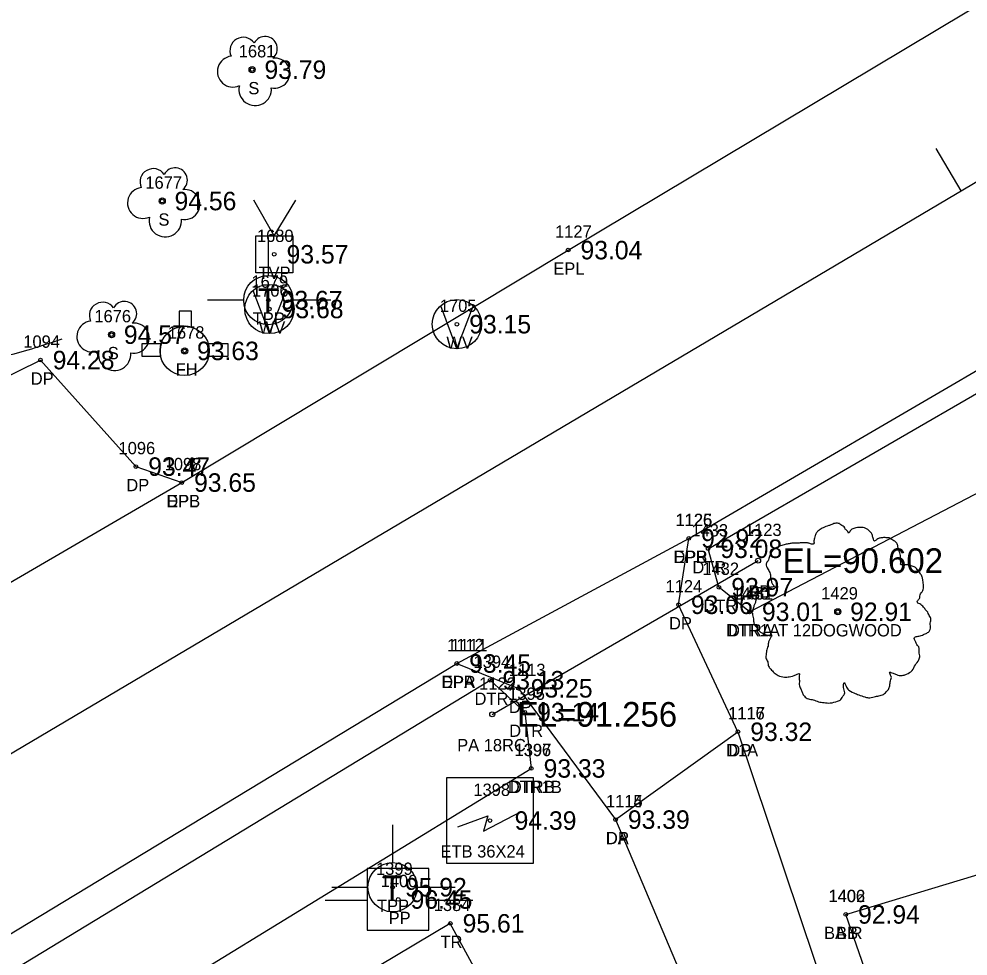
# Model space of a CAD drawing. Extents: x 2529517 to 2532038, y 935000 to 936944.
# Drawn here: x 2530911.6 to 2530988.7, y 935818.5 to 935894.6 of the extents above; entities that cross this region are included whole.
import ezdxf

# ---------------------------------------------------------------- set-up
doc = ezdxf.new("R2010")
doc.units = 0
for name, color, linetype in [('Default', 7, 'Continuous'), ('RD_EX_Bldg', 7, 'Continuous'), ('RD_EX_Bldg_txCode', 7, 'Continuous'), ('RD_EX_BldgApp', 7, 'Continuous'), ('RD_EX_DR_Pipe', 7, 'Continuous'), ('RD_EX_DR_Pipe_txCode', 7, 'Continuous'), ('RD_EX_Driveway', 7, 'Continuous'), ('RD_EX_Driveway_txCode', 7, 'Continuous'), ('RD_EX_H2O', 7, 'Continuous'), ('RD_EX_H2O_txCode', 7, 'Continuous'), ('RD_EX_Road', 7, 'Continuous'), ('RD_EX_Road_txCode', 7, 'Continuous'), ('RD_EX_TX_Bldg_ELEV', 7, 'Continuous'), ('RD_EX_TX_Driveway_ELEV', 7, 'Continuous'), ('RD_EX_TX_H2O_ELEV', 7, 'Continuous'), ('RD_EX_TX_Road_ELEV', 7, 'Continuous'), ('RD_EX_TX_UT_ELEV', 7, 'Continuous'), ('RD_EX_TX_VEG_ELEV', 7, 'Continuous'), ('RD_EX_UT', 7, 'Continuous'), ('RD_EX_UT_txCode', 7, 'Continuous'), ('RD_EX_VEG', 7, 'Continuous'), ('RD_EX_VEG_txCode', 7, 'Continuous'), ('RD_HC_Cl', 7, 'Continuous'), ('RD_HC_Data_Tic', 7, 'Continuous'), ('RD_HC_Survey_ELEV', 7, 'Continuous'), ('RD_SMD_Locator', 7, 'Continuous'), ('RD_TX_Pipe_ElevEX', 7, 'Continuous')]:
    doc.layers.add(name, color=color, linetype=linetype)

msp = doc.modelspace()

# ---------------------------------------------------------------- linework, layer by layer
at = {"layer": 'Default'}
msp.add_line((2530557.048, 935625.341), (2531768.068, 936342.554), dxfattribs=at)
at = {"layer": 'RD_EX_Bldg'}
msp.add_lwpolyline([(2530978.74, 935821.888), (2531008.107, 935830.756), (2531025.169, 935791.245), (2530993.411, 935779.732), (2530978.74, 935821.888)], dxfattribs=at)
at = {"layer": 'RD_EX_BldgApp'}
msp.add_open_spline([(2530899.082, 935867.283), (2530901.086, 935868.382), (2530905.768, 935865.432), (2530915.133, 935868.613)], degree=2, dxfattribs=at)
at = {"layer": 'RD_EX_DR_Pipe'}
msp.add_line((2530950.041, 935838.132), (2530971.625, 935850.61), dxfattribs=at)
at = {"layer": 'RD_EX_Driveway'}
for points in [[(2530835.179, 935834.103), (2530836.459, 935832.711), (2530846.318, 935840.723), (2530852.092, 935850.74), (2530868.321, 935858.234), (2530887.307, 935854.067), (2530913.359, 935866.894), (2530921.115, 935858.246), (2530924.837, 935856.951)], [(2530947.168, 935842.26), (2530952.171, 935840.244), (2530960.057, 935829.588), (2530969.992, 935836.718), (2530965.176, 935847.029), (2530966.001, 935852.419)], [(2530969.992, 935836.718), (2530982.506, 935799.382), (2530996.456, 935758.017)], [(2530960.057, 935829.588), (2530973.324, 935798.15), (2530986.134, 935754.257)]]:
    msp.add_lwpolyline(points, dxfattribs=at)
at = {"layer": 'RD_EX_H2O'}
msp.add_line((2530970.94, 935846.455), (2530996.778, 935859.952), dxfattribs=at)
for points in [[(2530970.94, 935846.455), (2530968.45, 935848.455), (2530967.561, 935851.576), (2530992.627, 935866.076), (2530995.026, 935864.088), (2530996.778, 935859.952)], [(2530882.813, 935800.188), (2530949.875, 935840.903), (2530952.688, 935838.305), (2530953.214, 935833.742)], [(2530882.813, 935800.188), (2530888.21, 935794.647), (2530891.364, 935795.844), (2530953.214, 935833.742)]]:
    msp.add_lwpolyline(points, dxfattribs=at)
at = {"layer": 'RD_EX_Road'}
for points in [[(2530213.129, 935600.159), (2530313.796, 935600.808), (2530414.146, 935601.135), (2530426.724, 935601.431), (2530429.462, 935603.551), (2530467.667, 935608.622), (2530486.463, 935612.382), (2530518.022, 935622.553), (2530522.163, 935623.679), (2530567.909, 935646.012), (2530609.299, 935670.154), (2530695.461, 935720.024), (2530775.853, 935769.269), (2530868.285, 935824.026), (2530924.837, 935856.951), (2530956.207, 935875.821), (2531040.717, 935926.378), (2531079.452, 935947.762)], [(2530212.444, 935579.718), (2530312.608, 935580.142), (2530402.982, 935580.636), (2530451.057, 935579.535), (2530466.913, 935580.348), (2530487.453, 935583.291), (2530533.43, 935598.455), (2530580.282, 935625.084), (2530621.694, 935649.225), (2530704.615, 935698.354), (2530718.668, 935706.376), (2530795.45, 935752.358), (2530871.328, 935796.67), (2530882.405, 935803.04), (2530947.168, 935842.26), (2530966.001, 935852.419), (2530992.723, 935868.002), (2531009.487, 935879.014), (2531052.394, 935904.854), (2531090.884, 935928.231)]]:
    msp.add_lwpolyline(points, dxfattribs=at)
at = {"layer": 'RD_EX_UT'}
for p, q in [((2530932.348, 935876.983), (2530930.682, 935879.869)), ((2530932.348, 935876.983), (2530934.089, 935879.869)), ((2530931.865, 935876.835), (2530931.865, 935873.765)), ((2530931.951, 935869.049), (2530930.647, 935872.531)), ((2530931.951, 935869.049), (2530933.273, 935872.494)), ((2530926.934, 935871.78), (2530929.865, 935871.78)), ((2530933.865, 935871.78), (2530936.934, 935871.78)), ((2530947.176, 935867.815), (2530945.872, 935871.297)), ((2530947.176, 935867.815), (2530948.498, 935871.26)), ((2530924.618, 935870.861), (2530924.618, 935869.587)), ((2530925.618, 935870.861), (2530924.618, 935870.861)), ((2530925.618, 935869.564), (2530925.618, 935870.861)), ((2530923.159, 935868.213), (2530921.601, 935868.213)), ((2530921.601, 935868.213), (2530921.601, 935867.213)), ((2530928.601, 935868.213), (2530926.991, 935868.213)), ((2530928.601, 935867.213), (2530928.601, 935868.213)), ((2530921.601, 935867.213), (2530923.121, 935867.213)), ((2530927.029, 935867.213), (2530928.601, 935867.213)), ((2530941.956, 935829.167), (2530941.956, 935826.098)), ((2530944.902, 935825.611), (2530939.902, 935825.611)), ((2530939.902, 935825.611), (2530939.902, 935820.611)), ((2530944.902, 935820.611), (2530944.902, 935825.611)), ((2530937.026, 935824.113), (2530939.956, 935824.113)), ((2530943.956, 935824.113), (2530947.026, 935824.113)), ((2530936.471, 935823.048), (2530939.94, 935823.048)), ((2530944.831, 935823.048), (2530948.471, 935823.048)), ((2530939.902, 935820.611), (2530944.902, 935820.611))]:
    msp.add_line(p, q, dxfattribs=at)
for points in [[(2530930.848, 935873.983), (2530930.848, 935876.983), (2530933.848, 935876.983), (2530933.848, 935873.983)], [(2530946.361, 935826.01), (2530946.361, 935833.01), (2530953.361, 935833.01), (2530953.361, 935826.01)]]:
    msp.add_lwpolyline(points, close=True, dxfattribs=at)
msp.add_lwpolyline([(2530947.26, 935829.004), (2530949.682, 935829.904), (2530949.336, 935828.658), (2530952.381, 935830.251)], dxfattribs=at)
for centre, radius in [((2530931.865, 935871.765), 2), ((2530931.951, 935871.041), 2), ((2530947.176, 935869.808), 2), ((2530925.075, 935867.64), 2), ((2530925.075, 935867.64), 0.25), ((2530941.956, 935824.098), 2)]:
    msp.add_circle(centre, radius, dxfattribs=at)
for start, end in [(74.24553, 103.21276), (163.3387, 192.31502), (347.68498, 16.6613)]:
    msp.add_arc((2530925.075, 935867.64), 2, start, end, dxfattribs=at)
at = {"layer": 'RD_EX_VEG'}
msp.add_lwpolyline([(2530909.492, 935692.948), (2530983.63, 935753.484), (2530946.64, 935821.165), (2530904.977, 935796.341), (2530852.836, 935733.758), (2530882.898, 935682.258)], dxfattribs=at)
for centre, radius in [((2530930.551, 935890.469), 0.25), ((2530923.252, 935879.805), 0.25), ((2530919.138, 935868.959), 0.25), ((2530978.099, 935846.458), 0.25), ((2530978.086, 935846.439), 0.0001)]:
    msp.add_circle(centre, radius, dxfattribs=at)
for centre, radius, start, end in [((2530929.83, 935892.016), 1.084, 34.97629, 204.75602), ((2530931.596, 935892.171), 0.995, 308.76261, 152.04674), ((2530928.987, 935890.314), 1.257, 96.45179, 294.73401), ((2530932.391, 935890.19), 1.218, 256.56668, 98.10463), ((2530930.797, 935888.873), 1.318, 166.88266, 5.75893), ((2530922.531, 935881.352), 1.084, 34.97629, 204.75602), ((2530924.297, 935881.507), 0.995, 308.76261, 152.04674), ((2530921.688, 935879.649), 1.257, 96.45179, 294.73401), ((2530925.092, 935879.525), 1.218, 256.56668, 98.10463), ((2530923.498, 935878.208), 1.318, 166.88266, 5.75893), ((2530918.417, 935870.506), 1.084, 34.97629, 204.75602), ((2530920.183, 935870.661), 0.995, 308.76261, 152.04674), ((2530917.574, 935868.803), 1.257, 96.45179, 294.73401), ((2530920.977, 935868.68), 1.218, 256.56668, 98.10463), ((2530919.383, 935867.363), 1.318, 166.88266, 5.75893)]:
    msp.add_arc(centre, radius, start, end, dxfattribs=at)
for points in [[(2530978.231, 935853.626), (2530977.931, 935853.651), (2530977.606, 935853.551), (2530977.356, 935853.451), (2530977.131, 935853.376), (2530976.906, 935853.276), (2530976.606, 935853.101), (2530976.382, 935852.901), (2530976.257, 935852.651), (2530976.207, 935852.426), (2530976.157, 935852.151), (2530976.157, 935851.976), (2530976.032, 935851.951), (2530975.882, 935851.976), (2530975.632, 935852.051), (2530975.382, 935852.051), (2530975.132, 935852.051), (2530974.782, 935852.026), (2530974.432, 935852.026), (2530974.158, 935851.976), (2530973.833, 935851.926), (2530973.458, 935851.801), (2530973.108, 935851.676), (2530972.808, 935851.426), (2530972.558, 935850.952), (2530972.433, 935850.602), (2530972.283, 935850.352), (2530972.433, 935849.902), (2530972.608, 935849.552), (2530972.633, 935849.352), (2530972.708, 935848.928), (2530972.808, 935848.703), (2530972.933, 935848.503), (2530972.858, 935848.478), (2530972.483, 935848.428), (2530972.183, 935848.328), (2530971.759, 935848.103), (2530971.534, 935847.878), (2530971.434, 935847.553), (2530971.409, 935847.203), (2530971.309, 935847.003), (2530971.234, 935846.729), (2530971.209, 935846.654), (2530971.159, 935846.329), (2530971.259, 935845.879), (2530971.284, 935845.529), (2530971.409, 935845.304), (2530971.559, 935845.129), (2530971.734, 935844.879), (2530972.133, 935844.654), (2530972.458, 935844.554), (2530972.658, 935844.53), (2530972.483, 935844.03), (2530972.433, 935843.68), (2530972.308, 935843.28), (2530972.308, 935843.205), (2530972.258, 935842.73), (2530972.408, 935842.405), (2530972.483, 935842.031), (2530972.658, 935841.806), (2530972.933, 935841.506), (2530973.258, 935841.281), (2530973.758, 935841.156), (2530974.158, 935841.181), (2530974.732, 935841.356), (2530974.982, 935841.431), (2530974.957, 935841.256), (2530974.982, 935840.881), (2530974.982, 935840.456), (2530975.132, 935840.131), (2530975.232, 935839.857), (2530975.382, 935839.607), (2530975.707, 935839.382), (2530976.107, 935839.307), (2530976.531, 935839.157), (2530976.981, 935839.082), (2530977.481, 935839.057), (2530978.081, 935839.207), (2530978.356, 935839.332), (2530978.456, 935839.507), (2530978.656, 935839.882), (2530978.606, 935840.106), (2530978.631, 935840.706), (2530978.73, 935840.531), (2530978.905, 935840.181), (2530979.405, 935839.882), (2530979.805, 935839.707), (2530980.28, 935839.557), (2530980.58, 935839.482), (2530981.054, 935839.557), (2530981.429, 935839.632), (2530981.804, 935839.757), (2530982.104, 935840.031), (2530982.279, 935840.306), (2530982.329, 935840.581), (2530982.404, 935840.956), (2530982.454, 935841.131)], [(2530982.454, 935841.131), (2530982.379, 935841.306), (2530982.329, 935841.556), (2530982.404, 935841.531), (2530982.579, 935841.481), (2530982.854, 935841.356), (2530983.079, 935841.281), (2530983.403, 935841.306), (2530983.678, 935841.406), (2530984.128, 935841.681), (2530984.403, 935842.156), (2530984.678, 935842.555), (2530984.753, 935842.88), (2530984.703, 935843.105), (2530984.678, 935843.605), (2530984.478, 935843.855), (2530984.428, 935843.98), (2530984.328, 935844.38), (2530984.403, 935844.43), (2530984.678, 935844.48), (2530985.053, 935844.604), (2530985.328, 935844.729), (2530985.553, 935844.904), (2530985.627, 935845.129), (2530985.603, 935845.529), (2530985.652, 935845.929), (2530985.578, 935846.079), (2530985.478, 935846.229), (2530985.403, 935846.429), (2530985.253, 935846.579), (2530985.153, 935846.729), (2530985.053, 935846.828), (2530984.928, 935846.978), (2530984.753, 935847.103), (2530984.603, 935847.153), (2530984.553, 935847.303), (2530984.703, 935847.503), (2530984.753, 935847.603), (2530984.778, 935847.828), (2530985.003, 935848.178), (2530985.053, 935848.578), (2530985.003, 935849.003), (2530984.953, 935849.277), (2530984.803, 935849.552), (2530984.603, 935849.802), (2530984.478, 935849.977), (2530984.303, 935850.102), (2530983.978, 935850.227), (2530983.728, 935850.277), (2530983.378, 935850.277), (2530983.179, 935850.327), (2530983.204, 935850.377), (2530983.204, 935850.527), (2530983.204, 935850.802), (2530983.129, 935851.252), (2530982.979, 935851.751), (2530982.979, 935851.776), (2530982.879, 935852.026), (2530982.654, 935852.226), (2530982.479, 935852.326), (2530982.279, 935852.451), (2530982.029, 935852.476), (2530981.729, 935852.476), (2530981.454, 935852.426), (2530981.254, 935852.326), (2530981.079, 935852.201), (2530981.004, 935852.351), (2530980.905, 935852.651), (2530980.855, 935852.801), (2530980.705, 935852.976), (2530980.48, 935853.176), (2530980.03, 935853.301), (2530979.405, 935853.226), (2530979.105, 935853.026), (2530978.955, 935852.851), (2530978.905, 935852.976), (2530978.705, 935853.176), (2530978.606, 935853.351), (2530978.431, 935853.476), (2530978.281, 935853.576), (2530978.181, 935853.626)]]:
    msp.add_spline(points, degree=3, dxfattribs=at)
at = {"layer": 'RD_HC_Cl'}
msp.add_line((2530557.048, 935625.341), (2531768.068, 936342.554), dxfattribs=at)
at = {"layer": 'RD_HC_Data_Tic'}
msp.add_line((2530988.111, 935880.633), (2530986.073, 935884.075), dxfattribs=at)
at = {"layer": 'RD_SMD_Locator'}
for centre, radius in [((2530930.551, 935890.469), 0.15), ((2530923.252, 935879.805), 0.15), ((2530956.207, 935875.821), 0.15), ((2530932.348, 935875.483), 0.15), ((2530931.865, 935871.765), 0.15), ((2530931.951, 935871.042), 0.15), ((2530947.176, 935869.808), 0.15), ((2530919.138, 935868.959), 0.15), ((2530925.075, 935867.64), 0.15), ((2530913.359, 935866.894), 0.15), ((2530921.115, 935858.246), 0.15), ((2530924.837, 935856.951), 0.15), ((2530924.837, 935856.951), 0.15), ((2530966.001, 935852.419), 0.15), ((2530966.001, 935852.419), 0.15), ((2530967.561, 935851.576), 0.15), ((2530971.625, 935850.61), 0.2), ((2530968.45, 935848.455), 0.15), ((2530965.176, 935847.029), 0.15), ((2530970.94, 935846.455), 0.15), ((2530970.94, 935846.455), 0.15), ((2530978.099, 935846.458), 0.15), ((2530947.168, 935842.26), 0.15), ((2530947.168, 935842.26), 0.15), ((2530949.875, 935840.903), 0.15), ((2530952.171, 935840.244), 0.15), ((2530950.041, 935838.132), 0.2), ((2530952.688, 935838.305), 0.15), ((2530969.992, 935836.718), 0.15), ((2530969.992, 935836.718), 0.15), ((2530953.214, 935833.742), 0.15), ((2530953.214, 935833.742), 0.15), ((2530949.861, 935829.51), 0.15), ((2530960.057, 935829.588), 0.15), ((2530960.057, 935829.588), 0.15), ((2530941.956, 935824.098), 0.15), ((2530942.411, 935823.102), 0.15), ((2530978.74, 935821.888), 0.15), ((2530978.74, 935821.888), 0.15), ((2530946.64, 935821.165), 0.15)]:
    msp.add_circle(centre, radius, dxfattribs=at)

# ---------------------------------------------------------------- texts
at = {"layer": 'RD_EX_Bldg_txCode'}
for s, p in [('1406', (2530977.331, 935822.888)), ('1402', (2530977.355, 935822.888)), ('BA R', (2530976.984, 935819.888)), ('BB', (2530977.961, 935819.888))]:
    msp.add_text(s, height=1, dxfattribs=at).set_placement(p)
at = {"layer": 'RD_EX_DR_Pipe_txCode'}
for s, p in [('1123', (2530970.562, 935852.61)), ('PB', (2530970.846, 935847.61)), ('1122', (2530948.978, 935840.132)), ('PA 18RC', (2530947.198, 935835.132))]:
    msp.add_text(s, height=1, dxfattribs=at).set_placement(p)
at = {"layer": 'RD_EX_Driveway_txCode'}
for s, p in [('1094', (2530911.973, 935867.894)), ('DP', (2530912.58, 935864.894)), ('1096', (2530919.705, 935859.246)), ('1097', (2530923.451, 935857.951)), ('DP', (2530920.335, 935856.246)), ('DPB', (2530923.585, 935854.951)), ('1125', (2530964.938, 935853.419)), ('DPB', (2530964.749, 935850.419)), ('1124', (2530964.113, 935848.029)), ('DP', (2530964.397, 935845.029)), ('1112', (2530946.388, 935843.26)), ('1113', (2530951.392, 935841.244)), ('DPA', (2530945.9, 935840.26)), ('DP', (2530951.392, 935838.244)), ('1116', (2530969.188, 935837.718)), ('1117', (2530969.212, 935837.718)), ('D1A', (2530969.031, 935834.718)), ('DP', (2530969.212, 935834.718)), ('1114', (2530959.278, 935830.588)), ('1115', (2530959.278, 935830.588)), ('DA', (2530959.262, 935827.588)), ('DP', (2530959.278, 935827.588))]:
    msp.add_text(s, height=1, dxfattribs=at).set_placement(p)
at = {"layer": 'RD_EX_H2O_txCode'}
for s, p in [('1433', (2530966.215, 935852.576)), ('DTR', (2530966.293, 935849.576)), ('1432', (2530967.104, 935849.455)), ('1430', (2530969.554, 935847.455)), ('1431', (2530969.877, 935847.455)), ('DTR', (2530967.183, 935846.455)), ('DTR1A', (2530969.019, 935844.455)), ('DTRA', (2530969.184, 935844.455)), ('1394', (2530948.528, 935841.903)), ('1395', (2530951.342, 935839.305)), ('DTR', (2530948.607, 935838.903)), ('DTR', (2530951.421, 935836.305)), ('1396', (2530951.844, 935834.742)), ('1397', (2530951.867, 935834.742)), ('DTR1B', (2530951.308, 935831.742)), ('DTRB', (2530951.474, 935831.742))]:
    msp.add_text(s, height=1, dxfattribs=at).set_placement(p)
at = {"layer": 'RD_EX_Road_txCode'}
for s, p in [('1127', (2530955.144, 935876.821)), ('EPL', (2530955.002, 935873.821)), ('1098', (2530923.451, 935857.951)), ('EPL', (2530923.632, 935854.951)), ('1126', (2530964.914, 935853.419)), ('EPR', (2530964.772, 935850.419)), ('1111', (2530946.672, 935843.26)), ('EPR', (2530945.939, 935840.26))]:
    msp.add_text(s, height=1, dxfattribs=at).set_placement(p)
at = {"layer": 'RD_EX_TX_Bldg_ELEV'}
msp.add_text('92.94', height=1.5, dxfattribs=at).set_placement((2530979.74, 935821.138))
msp.add_text('92.94', height=1.5, dxfattribs=at).set_placement((2530979.74, 935821.138))
at = {"layer": 'RD_EX_TX_Driveway_ELEV'}
for s, p in [('94.28', (2530914.359, 935866.144)), ('93.47', (2530922.115, 935857.496)), ('93.65', (2530925.837, 935856.201)), ('92.92', (2530967.001, 935851.669)), ('93.06', (2530966.176, 935846.279)), ('93.45', (2530948.168, 935841.51)), ('93.25', (2530953.171, 935839.494)), ('93.32', (2530970.992, 935835.968)), ('93.32', (2530970.992, 935835.968)), ('93.39', (2530961.057, 935828.838)), ('93.39', (2530961.057, 935828.838))]:
    msp.add_text(s, height=1.5, dxfattribs=at).set_placement(p)
at = {"layer": 'RD_EX_TX_H2O_ELEV'}
for s, p in [('93.08', (2530968.561, 935850.826)), ('92.97', (2530969.45, 935847.705)), ('93.01', (2530971.94, 935845.705)), ('93.01', (2530971.94, 935845.705)), ('93.13', (2530950.875, 935840.153)), ('93.14', (2530953.688, 935837.555)), ('93.33', (2530954.214, 935832.992)), ('93.33', (2530954.214, 935832.992))]:
    msp.add_text(s, height=1.5, dxfattribs=at).set_placement(p)
at = {"layer": 'RD_EX_TX_Road_ELEV'}
for s, p in [('93.04', (2530957.207, 935875.071)), ('93.65', (2530925.837, 935856.201)), ('92.92', (2530967.001, 935851.669)), ('93.45', (2530948.168, 935841.51))]:
    msp.add_text(s, height=1.5, dxfattribs=at).set_placement(p)
at = {"layer": 'RD_EX_TX_UT_ELEV'}
for s, p in [('93.57', (2530933.348, 935874.733)), ('93.67', (2530932.865, 935871.015)), ('93.68', (2530932.951, 935870.292)), ('93.15', (2530948.176, 935869.058)), ('93.63', (2530926.075, 935866.89)), ('94.39', (2530951.861, 935828.76)), ('95.92', (2530942.956, 935823.348))]:
    msp.add_text(s, height=1.5, dxfattribs=at).set_placement(p)
at = {"layer": 'RD_EX_TX_VEG_ELEV'}
for s, p in [('93.79', (2530931.551, 935889.719)), ('94.56', (2530924.252, 935879.055)), ('94.57', (2530920.138, 935868.209)), ('92.91', (2530979.099, 935845.708)), ('95.61', (2530947.64, 935820.415))]:
    msp.add_text(s, height=1.5, dxfattribs=at).set_placement(p)
at = {"layer": 'RD_EX_UT'}
for p in [(2530931.015, 935870.718), (2530941.107, 935823.05)]:
    msp.add_text('T', height=2, dxfattribs=at).set_placement(p)
at = {"layer": 'RD_EX_UT_txCode'}
for s, p in [('1680', (2530930.939, 935876.483)), ('TVP', (2530931.065, 935873.483)), ('1679', (2530930.495, 935872.765)), ('1706', (2530930.541, 935872.042)), ('1705', (2530945.79, 935870.808)), ('TPP', (2530930.597, 935869.765)), ('1678', (2530923.705, 935868.64)), ('WV', (2530931.092, 935869.042)), ('WV', (2530946.318, 935867.808)), ('FH', (2530924.342, 935865.64)), ('1398', (2530948.515, 935831.51)), ('ETB 36X24', (2530945.845, 935826.51)), ('1399', (2530940.61, 935825.098)), ('1400', (2530940.986, 935824.102)), ('TPP', (2530940.688, 935822.098)), ('PP', (2530941.632, 935821.102))]:
    msp.add_text(s, height=1, dxfattribs=at).set_placement(p)
at = {"layer": 'RD_EX_VEG_txCode'}
for s, p in [('1681', (2530929.465, 935891.469)), ('S', (2530930.244, 935888.469)), ('1677', (2530921.882, 935880.805)), ('S', (2530922.945, 935877.805)), ('1676', (2530917.744, 935869.959)), ('S', (2530918.831, 935866.959)), ('1429', (2530976.752, 935847.458)), ('T 12DOGWOOD', (2530973.256, 935844.458)), ('1384', (2530945.294, 935822.165)), ('TR', (2530945.845, 935819.165))]:
    msp.add_text(s, height=1, dxfattribs=at).set_placement(p)
at = {"layer": 'RD_HC_Survey_ELEV'}
msp.add_text('96.45', height=1.5, dxfattribs=at).set_placement((2530943.411, 935822.352))
at = {"layer": 'RD_TX_Pipe_ElevEX'}
for s, p in [('EL=90.602', (2530973.625, 935849.61)), ('EL=91.256', (2530952.041, 935837.132))]:
    msp.add_text(s, height=2, dxfattribs=at).set_placement(p)

doc.saveas('drawing.dxf')
